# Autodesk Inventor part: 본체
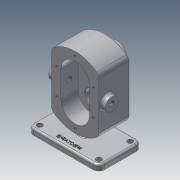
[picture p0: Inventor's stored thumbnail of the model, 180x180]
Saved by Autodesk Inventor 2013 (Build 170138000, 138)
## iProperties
Created: 2019-03
Part Number: 본체
Material: 알루미늄 6061
Document SubType Name: Modeling
Designer: Administrator
Density: 2.71 g/cm^3
Mass: 1191.51 g
Surface Area: 719.254 cm^2
Volume: 439.671 cm^3
Author: Administrator
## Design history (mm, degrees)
sketch "스케치1"
  geometry: L1 (-40, 44.721)-(-40, -44.721); L2 (40, 44.721)-(40, -44.721); A1 r 60 centre (0, 0) between (-40, -44.721) and (40, -44.721); A2 r 60 centre (0, 0) between (40, 44.721) and (-40, 44.721); 1 further point
  constraints: 4 end point, 4 point on circle, 2 centre point, 1 coincident, 1 parallel, 1 vertical
  dimensions: "d1" = 40 distance from line of A1.centre L1; "d2" = 40 distance from line of L2 point (0, 0); "d3" = 60 radius of A2; "d4" = 60 radius of A1
extrude "돌출1" new body sketch "스케치1" stored distance "d5" = 53; taper "d6" = 0 deg
sketch "스케치2"
  geometry: L1 (40, -44.721)-(40, 44.721) reference; L2 (0, 0)-(0, 78); L3 (60, 68)-(-60, 68); L4 (-60, 68)-(-60, 78); L5 (-60, 78)-(60, 78); L6 (60, 78)-(60, 68); A1 r 60 centre (0, 0) between (40, 44.721) and (-40, 44.721) reference
  constraints: 10 end point, 3 parallel, 1 horizontal, 1 midpoint, 1 perpendicular
  dimensions: "d7" = 78 distance of L2.end L2.start; "d8" = 120 distance of L4.end L5.end; "d9" = 10 distance of L3.end L4.end
extrude "돌출2" join sketch "스케치2" distance "d10" = 73; taper "d11" = 0 deg
sketch "스케치3"
  geometry: L1 (120, 0)-(0, 0) reference; L2 (54, 0)-(66, 0); L3 (66, 0)-(66, -43); L4 (66, -43)-(54, -43); L5 (54, -43)-(54, 0); 2 further points
  constraints: 8 end point, 2 midpoint, 2 parallel, 1 horizontal, 1 perpendicular
  dimensions: "d12" = 12 distance of L3.end L4.end; "d13" = 43 distance of L2.end L3.end
extrude "돌출3" join sketch "스케치3" stored distance "d14" = 73; taper "d15" = 0 deg
sketch "스케치4"
  geometry: L1 (-40, 44.721)-(-40, -44.721) reference; L2 (0, 0)-(0, -22); L3 (0, 0)-(0, 22); L4 (24, -22)-(24, 22); L5 (-24, -22)-(-24, 22); A1 r 60 centre (0, 0) between (-40, -44.721) and (40, -44.721) reference; A2 r 24 centre (0, -22) between (24, -22) and (-24, -22); A3 r 24 centre (0, 22) between (24, 22) and (-24, 22)
  constraints: 8 end point, 4 point on circle, 3 tangent, 2 centre point, 2 coincident, 2 parallel, 1 collinear
  dimensions: "d16" = 22 distance of L2.start L2.end; "d17" = 22 distance of L2.start L3.end; "d18" = 48 diameter of A2; "d19" = 48 diameter of A3
extrude "돌출4" cut sketch "스케치4" distance "d20" = 29; taper "d21" = 0 deg
sketch "스케치5"
  geometry: C1 r 12.5 at (0, 22); A1 r 24 centre (0, 22) between (24, 22) and (-24, 22) reference; 1 further point
  constraints: 1 centre point, 1 coincident
  dimensions: "d22" = 25 diameter of C1
extrude "돌출5" cut sketch "스케치5" distance "d23" = 15; taper "d24" = 0 deg
sketch "스케치6"
  geometry: C1 r 12.5 at (0, -22); A1 r 24 centre (0, -22) between (-24, -22) and (24, -22) reference; 1 further point
  constraints: 1 centre point, 1 coincident
  dimensions: "d25" = 25 diameter of C1
extrude "돌출6" cut sketch "스케치6" distance "d26" = 15; taper "d27" = 0 deg
sketch "스케치7"
  geometry: L1 (6, 68)-(6, 59.699) reference; L2 (0, 0)-(0, -22); C1 r 19 at (0, -22); A1 r 60 centre (0, 0) between (40, 44.721) and (6, 59.699) reference
  constraints: 2 end point, 1 centre point, 1 coincident, 1 parallel
  dimensions: "d28" = 22 distance of L2.start L2.end; "d29" = 38 diameter of C1
extrude "돌출7" join sketch "스케치7" distance "d30" = 17; taper "d31" = 0 deg
sketch "스케치8"
  geometry: C1 r 19 at (0, 0) reference; C2 r 14 at (0, 0); 1 further point
  constraints: 1 centre point, 1 coincident
  dimensions: "d32" = 28 diameter of C2
extrude "돌출8" cut sketch "스케치8" distance "d33" = 7.3; taper "d34" = 0 deg
sketch "스케치9"
  geometry: C1 r 14 at (0, 0) reference; C2 r 8.5 at (0, 0); 1 further point
  constraints: 1 centre point, 1 coincident
  dimensions: "d35" = 17 diameter of C2
extrude "돌출9" cut sketch "스케치9" stored distance "d36" = 7.3; taper "d37" = 0 deg
fillet "모깎기1" dims "d38" = 10
sketch "스케치10"
  geometry: A1 r 24 centre (0, 22) between (24, 22) and (-24, 22) reference; A2 r 24 centre (0, -22) between (-24, -22) and (24, -22) reference; A3 r 31 centre (0, -22) between (0, -53) and (31, -22); A4 r 31 centre (0, 22) between (-31, 22) and (31, 22); 2 further points
  constraints: 6 point on circle, 2 centre point, 2 coincident
  dimensions: "d39" = 62 diameter of A3; "d40" = 62 diameter of A4
hole "구멍1" sketch "스케치10" at (0, -53), (31, -22), (-31, -22), (-31, 22), (31, 22), (0, 53) diameter "d41" = 4.134; stored, may be unused: countersink angle "d45" = 90 deg, drill point angle "d47" = 118 deg; dims "d42" = 10, "d43" = 4, "d44" = 2, "d46" = 12
sketch "스케치11"
  geometry: L1 (53, 89.443)-(53, 0) reference; L2 (10, 122.721)-(63, 122.721) reference; C1 r 11 at (39, 44.721); 1 further point
  constraints: 1 centre point
  dimensions: "d48" = 22 diameter of C1; "d49" = 78 distance from line of C1.centre L2; "d50" = 14 distance from line of C1.centre L1
extrude "돌출10" join sketch "스케치11" distance "d51" = 8; taper "d52" = 0 deg
sketch "스케치12"
  geometry: C1 r 11 at (0, 0) reference; 2 further points
  constraints: 1 coincident
hole "구멍2" sketch "스케치12" at (0, 0) diameter "d53" = 8.376; stored, may be unused: countersink angle "d57" = 90 deg, drill point angle "d59" = 118 deg; dims "d54" = 10, "d55" = 4, "d56" = 2, "d58" = 12
sketch "스케치13"
  geometry: C1 r 4.5 at (-44, 33); C2 r 4.5 at (56, 33); C3 r 4.5 at (56, -20); C4 r 4.5 at (-44, -20); A1 r 10 centre (-44, 33) between (-44, 43) and (-54, 33) reference; A2 r 10 centre (-44, -20) between (-54, -20) and (-44, -30) reference; A3 r 10 centre (56, -20) between (56, -30) and (66, -20) reference; A4 r 10 centre (56, 33) between (66, 33) and (56, 43) reference; 1 further point
  constraints: 4 centre point, 4 coincident
  dimensions: "d60" = 9 diameter of C1; "d61" = 9 diameter of C2; "d62" = 9 diameter of C3; "d63" = 9 diameter of C4
extrude "돌출11" cut sketch "스케치13" stored distance "d64" = 8; taper "d65" = 0 deg
fillet "모깎기2" dims "d66" = 10
chamfer "모따기1" distance "d67" = 1; stored, may be unused: second distance "d68" = 2, angle "d69" = 45 deg
chamfer "모따기2" distance "d70" = 0.7; stored, may be unused: second distance "d71" = 2, angle "d72" = 30 deg
fillet "모깎기3" dims "d73" = 0.5
fillet "모깎기4" dims "d74" = 3
fillet "모깎기5" dims "d75" = 3
fillet "모깎기6" dims "d76" = 3
fillet "모깎기7" dims "d77" = 3
fillet "모깎기8" dims "d78" = 3
sketch "스케치14"
  geometry: L1 (-10, 60)-(-10, 7) reference; L2 (0, -3)-(100, -3) reference; A1 r 7 centre (0, 7) between (-7, 7) and (0, 0) reference; 2 further points
  constraints: 1 horizontal alignment, 1 other
  dimensions: "d79" = 60 distance from line of point (50, 7) L1; "d83" = 10 distance from line of L2 point (50, 7) (derived)
feature "엠보싱1" sketch "스케치14" dims "d80" = 0.5, "d81" = 0
fillet "모깎기9" dims "d82" = 3
node "솔리드1"
mirror "대칭1"
